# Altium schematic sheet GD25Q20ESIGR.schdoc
size 127 x 101 mm
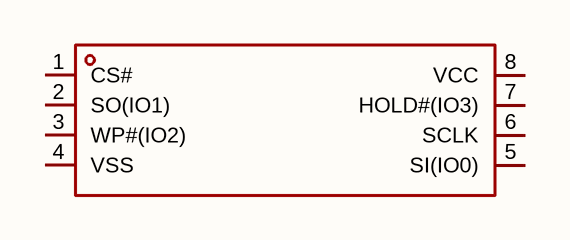
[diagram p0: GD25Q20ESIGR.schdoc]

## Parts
U?  gd25q20esigr  [SOIC-8_L5.3-W5.3-P1.27-LS8.0-BL]  (value not drawn)

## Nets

Not connected (* = marked no-connect by the designer): U? 1(CS#) 2(SO(IO1)) 3(WP#(IO2)) 4(VSS) 5(SI(IO0)) 6(SCLK) 7(HOLD#(IO3)) 8(VCC)

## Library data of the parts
U? = gd25q20esigr: 接口类型:SPI;存储容量:2Mbit;时钟频率(fc):133MHz;; Manufacturer: GigaDevice(兆易创新); AddInBom: yes; ModelId: f83d990ad74f400caf5ac920b7771508; ModelName: SOIC-8_L5.3-W5.3-H1.9-LS7.9-P1.27; ModelTransform: 208.661,311.25654,0,0,0,0,-0.0005,0.0005,0; Interface: SPI; Memory Size: 2Mbit; Clock Frequency: 133MHz; Voltage - Supply: 2.7V~3.6V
